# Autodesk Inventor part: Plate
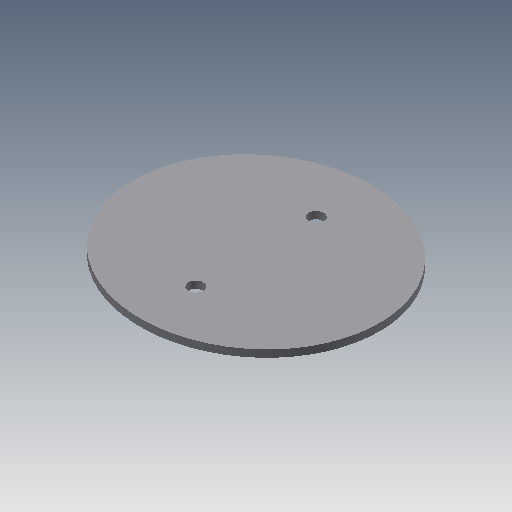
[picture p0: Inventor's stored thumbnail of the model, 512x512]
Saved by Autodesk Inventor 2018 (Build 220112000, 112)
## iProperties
Created: 2009-04
Part Number: Plate
Document SubType Name: Modeling
Designer: Sham
Density: 1 g/cm^3
Material: Generic
Appearance: Default
Author: Sham
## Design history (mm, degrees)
sketch "Sketch1"
  geometry: C1 r 6.25 at (-50, 0); C2 r 6.25 at (50, 0); 4 further points; 1 other entity
  constraints: 2 centre point, 1 coincident, 5 other
  dimensions: "d1" = 12.5 diameter of C1; "d2" = 12.5 diameter of C2; "d3" = 100 distance of C2.centre C1.centre; "d4" = 102.5 distance of point (0, 0) point (0, 102.5); "d5" = 96 distance of point (0, 0) point (-96, 0); "d6" = 50 distance of point (0, 0) C1.centre
extrude "Extrusion1" new body sketch "Sketch1" distance "d7" = 6; taper "d8" = 0 deg
body "Solid1"
